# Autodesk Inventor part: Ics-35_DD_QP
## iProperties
Created: 2007-02
Part Number: Ics-35_DD_QP
Checked By: Alves
Material: nicht zugewiesen
Description: XX BENENNUNG XX
Document SubType Name: Modellieren
Designer: Klein
ME: ST
Title: XX Gruppe XX
Author: Klein
Comments: keine Bemerkung
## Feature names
1. Grundkörper [Extrusion]
2. Grundkörperkontur [Extrusion]
3. Vertiefung [Extrusion]
4. Sensoraufnahme [Extrusion]
5. Extrusion6
6. Drehung2 [Revolution]
7. Extrusion7
8. Rundung1 [Fillet]
9. Extrusion8
10. Extrusion9
11. Rundung2 [Fillet]
12. 2 LED Fenster [Extrusion]
13. Drehung1 [Revolution]
